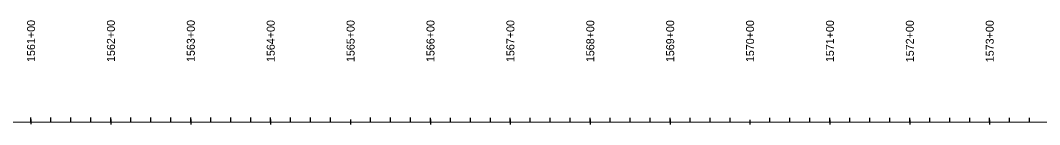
# Model space of a CAD drawing. Extents: x 21596470 to 21601942, y 8263806 to 8275912.
# Drawn here: x 21599406 to 21600682, y 8275781 to 8275912 of the extents above; entities that cross this region are included whole.
import ezdxf

# ---------------------------------------------------------------- set-up
doc = ezdxf.new("R2010")
doc.units = 0
for name, color, linetype in [('Level 1', 7, 'Continuous'), ('Level 20', 7, 'Continuous'), ('wetNoteSoil', 7, 'Continuous')]:
    doc.layers.add(name, color=color, linetype=linetype)

msp = doc.modelspace()

# ---------------------------------------------------------------- linework, layer by layer
at = {"layer": 'Level 1'}
for p, q in [((21599419.3, 8275784.8), (21599419.3, 8275790.3)), ((21599519.3, 8275784.8), (21599519.3, 8275790.2)), ((21599619.3, 8275784.8), (21599619.3, 8275790.2)), ((21599719.3, 8275784.7), (21599719.3, 8275790.2)), ((21599919.3, 8275784.7), (21599919.3, 8275790.1)), ((21600019.3, 8275784.7), (21600019.3, 8275790.1)), ((21600119.3, 8275784.6), (21600119.3, 8275790.1)), ((21600219.3, 8275784.6), (21600219.3, 8275790.1)), ((21600419.3, 8275784.6), (21600419.3, 8275790)), ((21600519.3, 8275784.5), (21600519.3, 8275790)), ((21600619.3, 8275784.5), (21600619.3, 8275790)), ((21599819.3, 8275787.8), (21599819.3, 8275781.6)), ((21600319.3, 8275787.6), (21600319.3, 8275781.5))]:
    msp.add_line(p, q, dxfattribs=at)
at = {"layer": 'Level 20'}
for p in [(21598714.2, 8275785), (21599270.9, 8275784.9)]:
    msp.add_line(p, (21601932.5, 8275784.2), dxfattribs=at)
at = {"layer": 'wetNoteSoil'}
for p, q in [((21599444.3, 8275784.8), (21599444.3, 8275790.3)), ((21599469.3, 8275784.8), (21599469.3, 8275790.3)), ((21599494.3, 8275784.8), (21599494.3, 8275790.3)), ((21599544.3, 8275784.8), (21599544.3, 8275790.2)), ((21599569.3, 8275784.8), (21599569.3, 8275790.2)), ((21599594.3, 8275784.8), (21599594.3, 8275790.2)), ((21599644.3, 8275784.8), (21599644.3, 8275790.2)), ((21599669.3, 8275784.7), (21599669.3, 8275790.2)), ((21599694.3, 8275784.7), (21599694.3, 8275790.2)), ((21599744.3, 8275784.7), (21599744.3, 8275790.2)), ((21599769.3, 8275784.7), (21599769.3, 8275790.2)), ((21599794.3, 8275784.7), (21599794.3, 8275790.2)), ((21599844.3, 8275784.7), (21599844.3, 8275790.2)), ((21599869.3, 8275784.7), (21599869.3, 8275790.2)), ((21599894.3, 8275784.7), (21599894.3, 8275790.2)), ((21599944.3, 8275784.7), (21599944.3, 8275790.1)), ((21599969.3, 8275784.7), (21599969.3, 8275790.1)), ((21599994.3, 8275784.7), (21599994.3, 8275790.1)), ((21600044.3, 8275784.7), (21600044.3, 8275790.1)), ((21600069.3, 8275784.6), (21600069.3, 8275790.1)), ((21600094.3, 8275784.6), (21600094.3, 8275790.1)), ((21600144.3, 8275784.6), (21600144.3, 8275790.1)), ((21600169.3, 8275784.6), (21600169.3, 8275790.1)), ((21600194.3, 8275784.6), (21600194.3, 8275790.1)), ((21600244.3, 8275784.6), (21600244.3, 8275790.1)), ((21600269.3, 8275784.6), (21600269.3, 8275790.1)), ((21600294.3, 8275784.6), (21600294.3, 8275790)), ((21600344.3, 8275784.6), (21600344.3, 8275790)), ((21600369.3, 8275784.6), (21600369.3, 8275790)), ((21600394.3, 8275784.6), (21600394.3, 8275790)), ((21600444.3, 8275784.5), (21600444.3, 8275790)), ((21600469.3, 8275784.5), (21600469.3, 8275790)), ((21600494.3, 8275784.5), (21600494.3, 8275790)), ((21600544.3, 8275784.5), (21600544.3, 8275790)), ((21600569.3, 8275784.5), (21600569.3, 8275790)), ((21600594.3, 8275784.5), (21600594.3, 8275790)), ((21600644.3, 8275784.5), (21600644.3, 8275790)), ((21600669.3, 8275784.5), (21600669.3, 8275790)), ((21599419.3, 8275787.9), (21599419.3, 8275781.8)), ((21599519.3, 8275787.8), (21599519.3, 8275781.7)), ((21599619.3, 8275787.8), (21599619.3, 8275781.7)), ((21599719.3, 8275787.8), (21599719.3, 8275781.7)), ((21599819.3, 8275787.8), (21599819.3, 8275781.6)), ((21599919.3, 8275787.7), (21599919.3, 8275781.6)), ((21600019.3, 8275787.7), (21600019.3, 8275781.6)), ((21600119.3, 8275787.7), (21600119.3, 8275781.6)), ((21600219.3, 8275787.7), (21600219.3, 8275781.5)), ((21600319.3, 8275787.6), (21600319.3, 8275781.5)), ((21600419.3, 8275787.6), (21600419.3, 8275781.5)), ((21600519.3, 8275787.6), (21600519.3, 8275781.5)), ((21600619.3, 8275787.6), (21600619.3, 8275781.4))]:
    msp.add_line(p, q, dxfattribs=at)

# ---------------------------------------------------------------- texts
at = {"layer": 'Level 1'}
for s, p in [('1565+00', (21599824.4, 8275859.7)), ('1570+00', (21600324.4, 8275859.6))]:
    msp.add_text(s, height=10.02, rotation=89.9853, dxfattribs=at).set_placement(p)
at = {"layer": 'wetNoteSoil'}
for s, p in [('1561+00', (21599424.4, 8275859.8)), ('1562+00', (21599524.4, 8275859.8)), ('1563+00', (21599624.4, 8275859.8)), ('1564+00', (21599724.4, 8275859.7)), ('1565+00', (21599824.4, 8275859.7)), ('1566+00', (21599924.4, 8275859.7)), ('1567+00', (21600024.4, 8275859.7)), ('1568+00', (21600124.4, 8275859.6)), ('1569+00', (21600224.4, 8275859.6)), ('1570+00', (21600324.4, 8275859.6)), ('1571+00', (21600424.4, 8275859.6)), ('1572+00', (21600524.4, 8275859.5)), ('1573+00', (21600624.4, 8275859.5))]:
    msp.add_text(s, height=10.02, rotation=89.9853, dxfattribs=at).set_placement(p)

doc.saveas('drawing.dxf')
